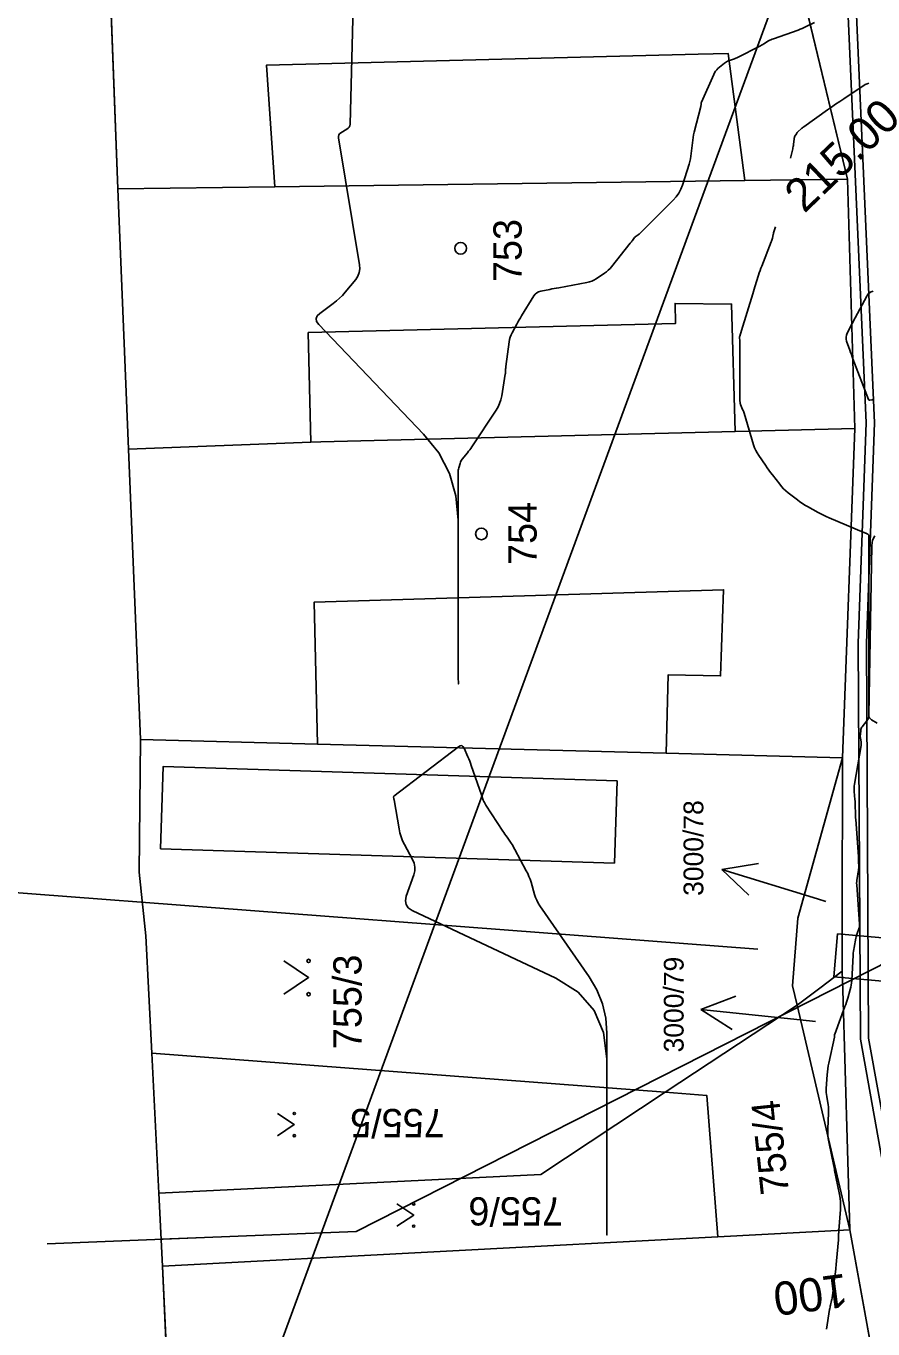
# Model space of a CAD drawing. Extents: x -534481 to -534256, y -1190577 to -1190138.
# Drawn here: x -534435.09 to -534409.62, y -1190436.66 to -1190397.49 of the extents above; entities that cross this region are included whole.
import ezdxf

# ---------------------------------------------------------------- set-up
doc = ezdxf.new("R2010")
doc.units = 0
for name, color, linetype in [('30', 7, 'Continuous'), ('31', 7, 'Continuous'), ('40', 7, 'Continuous'), ('_N_text', 7, 'Continuous'), ('_přístup', 7, 'Continuous'), ('_tenka', 7, 'Continuous'), ('Hranice parcel', 7, 'Continuous'), ('Parcelní čísla', 7, 'Continuous'), ('Polygon budovy', 7, 'Continuous'), ('Pop  PČ popisy', 7, 'Continuous'), ('Vnitřní kresba', 7, 'Continuous'), ('Vrstva 2', 7, 'Continuous'), ('Značky budov', 7, 'Continuous'), ('Značky kultur', 7, 'Continuous')]:
    doc.layers.add(name, color=color, linetype=linetype)

msp = doc.modelspace()

# ---------------------------------------------------------------- linework, layer by layer
at = {"layer": '30'}
for points in [[(-534412.097, -1190401.462), (-534412.031, -1190401.184), (-534412.024, -1190401.15), (-534412.018, -1190401.117), (-534412.012, -1190401.083), (-534412.008, -1190401.049), (-534411.99, -1190400.888), (-534411.987, -1190400.867), (-534411.981, -1190400.846), (-534411.973, -1190400.826), (-534411.963, -1190400.806), (-534411.918, -1190400.73), (-534411.906, -1190400.712), (-534411.893, -1190400.694), (-534411.879, -1190400.678), (-534411.863, -1190400.662), (-534411.781, -1190400.585), (-534411.762, -1190400.567), (-534411.742, -1190400.55), (-534411.721, -1190400.534), (-534411.7, -1190400.519), (-534410.987, -1190400.016), (-534410.864, -1190399.93), (-534410.741, -1190399.845), (-534410.617, -1190399.761), (-534410.492, -1190399.678), (-534409.853, -1190399.254), (-534409.797, -1190399.225), (-534409.746, -1190399.212)], [(-534409.49, -1190418.456), (-534409.659, -1190418.354), (-534409.696, -1190418.326), (-534409.722, -1190418.292), (-534409.738, -1190418.251), (-534409.743, -1190418.205), (-534409.743, -1190412.814), (-534409.745, -1190412.8), (-534409.75, -1190412.787), (-534409.759, -1190412.777), (-534409.772, -1190412.769), (-534409.83, -1190412.742), (-534409.845, -1190412.735), (-534409.86, -1190412.728), (-534409.874, -1190412.722), (-534409.889, -1190412.716), (-534410.937, -1190412.277), (-534411.021, -1190412.241), (-534411.103, -1190412.202), (-534411.185, -1190412.161), (-534411.265, -1190412.118), (-534411.586, -1190411.939), (-534411.664, -1190411.894), (-534411.739, -1190411.846), (-534411.813, -1190411.795), (-534411.885, -1190411.742), (-534412.17, -1190411.523), (-534412.239, -1190411.466), (-534412.304, -1190411.405), (-534412.365, -1190411.34), (-534412.421, -1190411.271), (-534412.641, -1190410.986), (-534412.695, -1190410.915), (-534412.748, -1190410.843), (-534412.8, -1190410.771), (-534412.851, -1190410.697), (-534413.053, -1190410.403), (-534413.101, -1190410.328), (-534413.142, -1190410.25), (-534413.177, -1190410.169), (-534413.206, -1190410.085), (-534413.494, -1190409.135), (-534413.504, -1190409.105), (-534413.514, -1190409.076), (-534413.525, -1190409.047), (-534413.537, -1190409.018), (-534413.601, -1190408.872), (-534413.606, -1190408.858), (-534413.61, -1190408.844), (-534413.613, -1190408.83), (-534413.616, -1190408.815), (-534413.623, -1190408.757), (-534413.624, -1190408.742), (-534413.625, -1190408.728), (-534413.626, -1190408.713), (-534413.626, -1190408.698), (-534413.621, -1190406.998), (-534413.621, -1190406.983), (-534413.621, -1190406.967), (-534413.622, -1190406.952), (-534413.623, -1190406.936), (-534413.629, -1190406.875), (-534413.63, -1190406.86), (-534413.629, -1190406.845), (-534413.627, -1190406.83), (-534413.623, -1190406.815), (-534413.571, -1190406.644), (-534413.23, -1190405.54), (-534413.166, -1190405.331), (-534413.058, -1190404.984), (-534413.036, -1190404.914), (-534413.013, -1190404.845), (-534412.988, -1190404.777), (-534412.962, -1190404.709), (-534412.678, -1190403.984), (-534412.668, -1190403.958), (-534412.659, -1190403.93), (-534412.651, -1190403.903), (-534412.644, -1190403.875), (-534412.619, -1190403.763), (-534412.612, -1190403.735), (-534412.605, -1190403.708), (-534412.597, -1190403.68), (-534412.589, -1190403.653), (-534412.552, -1190403.534)], [(-534409.564, -1190412.815), (-534409.631, -1190412.948), (-534409.655, -1190413.113), (-534409.741, -1190418.207), (-534409.746, -1190418.254), (-534409.757, -1190418.299), (-534409.776, -1190418.34), (-534409.802, -1190418.38), (-534409.943, -1190418.561), (-534409.96, -1190418.585), (-534409.972, -1190418.611), (-534409.981, -1190418.638), (-534409.986, -1190418.667), (-534409.998, -1190418.788), (-534410, -1190418.816), (-534410, -1190418.844), (-534409.999, -1190418.873), (-534409.995, -1190418.901), (-534409.977, -1190419.014), (-534409.974, -1190419.042), (-534409.973, -1190419.07), (-534409.974, -1190419.098), (-534409.978, -1190419.126), (-534410.172, -1190420.287), (-534410.179, -1190420.342), (-534410.183, -1190420.398), (-534410.183, -1190420.453), (-534410.18, -1190420.509), (-534410.159, -1190420.745), (-534410.155, -1190420.795), (-534410.152, -1190420.845), (-534410.15, -1190420.894), (-534410.149, -1190420.944), (-534410.145, -1190421.144), (-534410.143, -1190421.194), (-534410.142, -1190421.244), (-534410.139, -1190421.294), (-534410.136, -1190421.344), (-534410.057, -1190422.459), (-534410.055, -1190422.498), (-534410.053, -1190422.536), (-534410.051, -1190422.575), (-534410.05, -1190422.613), (-534410.047, -1190422.767), (-534410.047, -1190422.806), (-534410.049, -1190422.844), (-534410.053, -1190422.882), (-534410.059, -1190422.92), (-534410.097, -1190423.123), (-534410.104, -1190423.169), (-534410.108, -1190423.216), (-534410.11, -1190423.263), (-534410.108, -1190423.31), (-534410.022, -1190424.498), (-534410.021, -1190424.534), (-534410.024, -1190424.57), (-534410.031, -1190424.605), (-534410.042, -1190424.639), (-534410.091, -1190424.776), (-534410.103, -1190424.81), (-534410.113, -1190424.845), (-534410.123, -1190424.88), (-534410.13, -1190424.916), (-534410.186, -1190425.194), (-534410.197, -1190425.253), (-534410.205, -1190425.311), (-534410.211, -1190425.37), (-534410.216, -1190425.429), (-534410.255, -1190426.19), (-534410.261, -1190426.257), (-534410.27, -1190426.324), (-534410.283, -1190426.39), (-534410.3, -1190426.455), (-534410.375, -1190426.715), (-534410.395, -1190426.779), (-534410.416, -1190426.844), (-534410.437, -1190426.908), (-534410.46, -1190426.971), (-534410.769, -1190427.798), (-534410.772, -1190427.806), (-534410.773, -1190427.813), (-534410.774, -1190427.821), (-534410.775, -1190427.829), (-534410.775, -1190427.86), (-534410.775, -1190427.868), (-534410.776, -1190427.876), (-534410.777, -1190427.884), (-534410.778, -1190427.892), (-534410.944, -1190428.67), (-534410.961, -1190428.757), (-534410.975, -1190428.845), (-534410.986, -1190428.934), (-534410.994, -1190429.023), (-534411.022, -1190429.432), (-534411.024, -1190429.495), (-534411.023, -1190429.557), (-534411.019, -1190429.619), (-534411.01, -1190429.68), (-534410.969, -1190429.927), (-534410.96, -1190429.988), (-534410.955, -1190430.05), (-534410.953, -1190430.112), (-534410.954, -1190430.175), (-534410.975, -1190430.646), (-534410.976, -1190430.745), (-534410.971, -1190430.844), (-534410.961, -1190430.942), (-534410.944, -1190431.039), (-534410.797, -1190431.775), (-534410.79, -1190431.806), (-534410.779, -1190431.868), (-534410.774, -1190431.888), (-534410.772, -1190431.899), (-534410.624, -1190432.622), (-534410.605, -1190432.733), (-534410.594, -1190432.845), (-534410.591, -1190432.958), (-534410.596, -1190433.071), (-534410.645, -1190433.704), (-534410.647, -1190433.728), (-534410.648, -1190433.751), (-534410.649, -1190433.774), (-534410.65, -1190433.797), (-534410.652, -1190433.889), (-534410.652, -1190433.912), (-534410.653, -1190433.935), (-534410.655, -1190433.958), (-534410.657, -1190433.981), (-534410.714, -1190434.619), (-534410.724, -1190434.732), (-534410.736, -1190434.844), (-534410.748, -1190434.957), (-534410.762, -1190435.069), (-534410.837, -1190435.673), (-534410.842, -1190435.708), (-534410.847, -1190435.742), (-534410.854, -1190435.776), (-534410.862, -1190435.81), (-534410.895, -1190435.945), (-534410.903, -1190435.979), (-534410.91, -1190436.013), (-534410.916, -1190436.047), (-534410.922, -1190436.082), (-534411.012, -1190436.668)]]:
    msp.add_lwpolyline(points, dxfattribs=at)
at = {"layer": '31'}
for points in [[(-534411.381, -1190397.388), (-534411.622, -1190397.509), (-534411.683, -1190397.538), (-534411.745, -1190397.565), (-534411.807, -1190397.591), (-534411.871, -1190397.614), (-534412.61, -1190397.873), (-534412.648, -1190397.888), (-534412.686, -1190397.904), (-534412.722, -1190397.922), (-534412.757, -1190397.942), (-534412.898, -1190398.027), (-534412.933, -1190398.048), (-534412.968, -1190398.068), (-534413.004, -1190398.087), (-534413.04, -1190398.106), (-534413.676, -1190398.431), (-534413.71, -1190398.447), (-534413.744, -1190398.463), (-534413.779, -1190398.476), (-534413.815, -1190398.489), (-534413.958, -1190398.535), (-534413.993, -1190398.548), (-534414.026, -1190398.565), (-534414.057, -1190398.584), (-534414.087, -1190398.607), (-534414.279, -1190398.773), (-534414.318, -1190398.81), (-534414.352, -1190398.852), (-534414.382, -1190398.896), (-534414.406, -1190398.945), (-534414.776, -1190399.782), (-534414.78, -1190399.793), (-534414.783, -1190399.803), (-534414.785, -1190399.814), (-534414.786, -1190399.825), (-534414.789, -1190399.869), (-534414.79, -1190399.88), (-534414.791, -1190399.891), (-534414.793, -1190399.902), (-534414.795, -1190399.913), (-534414.993, -1190400.688), (-534415.012, -1190400.766), (-534415.028, -1190400.846), (-534415.04, -1190400.925), (-534415.05, -1190401.006), (-534415.082, -1190401.328), (-534415.092, -1190401.408), (-534415.107, -1190401.488), (-534415.125, -1190401.566), (-534415.148, -1190401.644), (-534415.349, -1190402.273), (-534415.398, -1190402.399), (-534415.46, -1190402.517), (-534415.537, -1190402.627), (-534415.627, -1190402.728), (-534416.627, -1190403.728), (-534416.639, -1190403.74), (-534416.652, -1190403.75), (-534416.665, -1190403.76), (-534416.679, -1190403.77), (-534416.736, -1190403.805), (-534416.75, -1190403.814), (-534416.763, -1190403.825), (-534416.774, -1190403.837), (-534416.785, -1190403.85), (-534416.854, -1190403.944), (-534416.869, -1190403.965), (-534416.884, -1190403.985), (-534416.899, -1190404.004), (-534416.915, -1190404.024), (-534417.476, -1190404.727), (-534417.525, -1190404.784), (-534417.578, -1190404.836), (-534417.635, -1190404.883), (-534417.695, -1190404.927), (-534417.946, -1190405.091), (-534418.01, -1190405.128), (-534418.077, -1190405.159), (-534418.147, -1190405.183), (-534418.219, -1190405.2), (-534419.069, -1190405.359), (-534419.136, -1190405.371), (-534419.204, -1190405.384), (-534419.271, -1190405.397), (-534419.339, -1190405.41), (-534419.608, -1190405.464), (-534419.672, -1190405.483), (-534419.728, -1190405.513), (-534419.775, -1190405.555), (-534419.816, -1190405.608), (-534420.184, -1190406.201), (-534420.222, -1190406.264), (-534420.259, -1190406.327), (-534420.296, -1190406.391), (-534420.331, -1190406.456), (-534420.47, -1190406.715), (-534420.502, -1190406.781), (-534420.527, -1190406.849), (-534420.546, -1190406.918), (-534420.559, -1190406.99), (-534420.657, -1190407.725), (-534420.659, -1190407.744), (-534420.661, -1190407.764), (-534420.663, -1190407.783), (-534420.664, -1190407.802), (-534420.667, -1190407.88), (-534420.668, -1190407.9), (-534420.67, -1190407.919), (-534420.672, -1190407.938), (-534420.675, -1190407.958), (-534420.783, -1190408.613), (-534420.808, -1190408.727), (-534420.845, -1190408.836), (-534420.892, -1190408.94), (-534420.951, -1190409.04), (-534421.684, -1190410.148), (-534421.714, -1190410.193), (-534421.745, -1190410.236), (-534421.778, -1190410.279), (-534421.811, -1190410.321), (-534421.971, -1190410.517), (-534421.991, -1190410.546), (-534422.009, -1190410.575), (-534422.024, -1190410.607), (-534422.035, -1190410.64), (-534422.075, -1190410.776), (-534422.083, -1190410.811), (-534422.089, -1190410.845), (-534422.093, -1190410.88), (-534422.094, -1190410.915), (-534422.094, -1190416.759), (-534422.094, -1190416.802), (-534422.094, -1190416.844), (-534422.093, -1190416.887), (-534422.092, -1190416.93), (-534422.088, -1190417.101), (-534422.087, -1190417.144), (-534422.086, -1190417.187), (-534422.086, -1190417.23), (-534422.085, -1190417.272), (-534422.086, -1190417.23), (-534422.086, -1190417.187), (-534422.087, -1190417.144), (-534422.088, -1190417.101), (-534422.092, -1190416.93), (-534422.093, -1190416.887), (-534422.094, -1190416.844), (-534422.094, -1190416.802), (-534422.094, -1190416.759), (-534422.094, -1190412.345), (-534422.159, -1190411.621), (-534422.354, -1190410.949), (-534422.678, -1190410.329), (-534423.131, -1190409.761), (-534426.285, -1190406.464), (-534426.349, -1190406.375), (-534426.365, -1190406.29), (-534426.334, -1190406.21), (-534426.256, -1190406.134), (-534425.85, -1190405.835), (-534425.752, -1190405.759), (-534425.659, -1190405.677), (-534425.572, -1190405.589), (-534425.49, -1190405.495), (-534425.174, -1190405.108), (-534425.107, -1190405.008), (-534425.066, -1190404.902), (-534425.049, -1190404.789), (-534425.057, -1190404.669), (-534425.691, -1190400.858), (-534425.692, -1190400.81), (-534425.681, -1190400.767), (-534425.656, -1190400.732), (-534425.617, -1190400.702), (-534425.437, -1190400.597), (-534425.397, -1190400.567), (-534425.368, -1190400.531), (-534425.351, -1190400.488), (-534425.344, -1190400.439), (-534425.133, -1190392.149)], [(-534409.609, -1190408.718), (-534409.623, -1190408.723), (-534409.638, -1190408.727), (-534409.653, -1190408.73), (-534409.713, -1190408.741), (-534409.727, -1190408.742), (-534409.738, -1190408.738), (-534409.747, -1190408.73), (-534409.754, -1190408.718), (-534410.219, -1190407.501), (-534410.244, -1190407.435), (-534410.268, -1190407.37), (-534410.292, -1190407.305), (-534410.315, -1190407.239), (-534410.411, -1190406.969), (-534410.426, -1190406.907), (-534410.429, -1190406.846), (-534410.418, -1190406.787), (-534410.394, -1190406.728), (-534410.24, -1190406.436), (-534410.149, -1190406.261), (-534409.807, -1190405.61), (-534409.771, -1190405.555), (-534409.725, -1190405.512), (-534409.671, -1190405.482), (-534409.608, -1190405.463)]]:
    msp.add_lwpolyline(points, dxfattribs=at)
msp.add_lwpolyline([(-534417.621, -1190427.776), (-534417.621, -1190433.845), (-534417.621, -1190428.541), (-534417.717, -1190427.753), (-534418.004, -1190427.087), (-534418.483, -1190426.543), (-534419.154, -1190426.12), (-534423.474, -1190424.08), (-534423.591, -1190424.003), (-534423.659, -1190423.907), (-534423.68, -1190423.791), (-534423.652, -1190423.654), (-534423.428, -1190423.016), (-534423.398, -1190422.896), (-534423.395, -1190422.779), (-534423.417, -1190422.664), (-534423.464, -1190422.55), (-534423.707, -1190422.101), (-534423.763, -1190421.987), (-534423.809, -1190421.87), (-534423.845, -1190421.749), (-534423.871, -1190421.625), (-534424.02, -1190420.753), (-534424.023, -1190420.735), (-534424.027, -1190420.717), (-534424.034, -1190420.68), (-534424.034, -1190420.672), (-534424.033, -1190420.664), (-534424.029, -1190420.657), (-534424.023, -1190420.651), (-534422.084, -1190419.159), (-534422.031, -1190419.13), (-534421.986, -1190419.127), (-534421.947, -1190419.151), (-534421.915, -1190419.202), (-534421.8, -1190419.46), (-534421.772, -1190419.524), (-534421.746, -1190419.59), (-534421.721, -1190419.655), (-534421.697, -1190419.722), (-534421.393, -1190420.603), (-534421.338, -1190420.764), (-534421.323, -1190420.804), (-534421.305, -1190420.842), (-534421.285, -1190420.879), (-534421.263, -1190420.915), (-534420.746, -1190421.695), (-534420.715, -1190421.741), (-534420.685, -1190421.786), (-534420.654, -1190421.832), (-534420.623, -1190421.877), (-534420.5, -1190422.059), (-534420.47, -1190422.104), (-534420.441, -1190422.151), (-534420.413, -1190422.198), (-534420.387, -1190422.246), (-534420.043, -1190422.888), (-534420, -1190422.972), (-534419.963, -1190423.059), (-534419.929, -1190423.147), (-534419.901, -1190423.237), (-534419.796, -1190423.601), (-534419.766, -1190423.691), (-534419.729, -1190423.777), (-534419.686, -1190423.86), (-534419.635, -1190423.939), (-534418.151, -1190426.079), (-534417.919, -1190426.472), (-534417.753, -1190426.886), (-534417.654, -1190427.32)], close=True, dxfattribs=at)
at = {"layer": '_N_text'}
msp.add_lwpolyline([(-534406.078, -1190512.511), (-534434.703, -1190456.89), (-534410.94, -1190392.232)], dxfattribs=at)
at = {"layer": '_přístup'}
msp.add_line((-534442.17, -1190423.028), (-534413.082, -1190425.244), dxfattribs=at)
msp.add_lwpolyline([(-534417.39, -1190422.659), (-534417.312, -1190420.188), (-534430.965, -1190419.755), (-534431.043, -1190422.227)], close=True, dxfattribs=at)
at = {"layer": '_tenka'}
for points in [[(-534405.407, -1190514.348), (-534394.258, -1190501.982), (-534392.12, -1190496.869), (-534393.492, -1190488.211), (-534397.35, -1190478.035), (-534403.219, -1190464.54), (-534405.491, -1190456.905), (-534409.051, -1190433.21), (-534409.998, -1190427.948), (-534410.066, -1190416.042), (-534409.827, -1190409.421), (-534410.645, -1190390.84)], [(-534405.057, -1190514.333), (-534394.044, -1190502.118), (-534391.862, -1190496.9), (-534393.249, -1190488.146), (-534397.118, -1190477.94), (-534402.983, -1190464.455), (-534405.247, -1190456.85), (-534408.804, -1190433.17), (-534409.748, -1190427.925), (-534409.816, -1190416.046), (-534409.577, -1190409.42), (-534410.397, -1190390.795)]]:
    msp.add_lwpolyline(points, dxfattribs=at)
at = {"layer": 'Hranice parcel'}
for p, q in [((-534410.38, -1190402.1), (-534412.44, -1190393.55)), ((-534432.64, -1190394.16), (-534432.33, -1190402.39)), ((-534410.16, -1190409.59), (-534410.38, -1190402.1)), ((-534432.33, -1190402.39), (-534432.01, -1190410.21)), ((-534410.53, -1190419.49), (-534410.16, -1190409.59)), ((-534432.01, -1190410.21), (-534431.64, -1190418.94)), ((-534415.87, -1190429.55), (-534411.9, -1190426.93)), ((-534410.31, -1190433.69), (-534411.9, -1190426.93)), ((-534431.3, -1190428.37), (-534415.87, -1190429.55)), ((-534431.3, -1190428.37), (-534431.09, -1190432.58)), ((-534431.09, -1190432.58), (-534430.98, -1190434.78)), ((-534414.28, -1190433.9), (-534430.98, -1190434.78)), ((-534410.31, -1190433.69), (-534414.28, -1190433.9)), ((-534407.58, -1190448.75), (-534410.31, -1190433.69)), ((-534430.98, -1190434.78), (-534430.23, -1190451.45))]:
    msp.add_line(p, q, dxfattribs=at)
for points in [[(-534432.33, -1190402.39), (-534427.61, -1190402.33), (-534413.47, -1190402.14), (-534410.38, -1190402.1)], [(-534432.01, -1190410.21), (-534426.52, -1190410), (-534426.22, -1190409.99), (-534413.76, -1190409.68), (-534410.16, -1190409.59)], [(-534431.64, -1190418.94), (-534431.68, -1190422.93), (-534431.48, -1190424.85), (-534431.3, -1190428.37)], [(-534431.64, -1190418.94), (-534426.32, -1190419.08), (-534415.84, -1190419.35), (-534410.53, -1190419.49)], [(-534411.9, -1190426.93), (-534412.04, -1190426.35), (-534411.88, -1190424.31), (-534410.53, -1190419.49)], [(-534410.53, -1190419.49), (-534410.54, -1190424.42), (-534410.54, -1190425.91)], [(-534411.9, -1190426.93), (-534411.22, -1190426.42), (-534410.54, -1190425.91)], [(-534410.54, -1190425.91), (-534410.52, -1190426.47), (-534410.31, -1190433.69)], [(-534431.09, -1190432.58), (-534419.61, -1190432.02), (-534415.87, -1190429.55)], [(-534415.87, -1190429.55), (-534414.61, -1190429.65), (-534414.28, -1190433.9)]]:
    msp.add_lwpolyline(points, dxfattribs=at)
at = {"layer": 'Polygon budovy'}
for points in [[(-534432.64, -1190394.16), (-534432.33, -1190402.39), (-534427.61, -1190402.33), (-534427.86, -1190398.67), (-534414.87, -1190398.34), (-534413.97, -1190398.32), (-534413.47, -1190402.14), (-534410.38, -1190402.1), (-534412.44, -1190393.55), (-534415.89, -1190393.7), (-534421.6, -1190393.94), (-534427.8, -1190394.2)], [(-534410.38, -1190402.1), (-534413.47, -1190402.14), (-534427.61, -1190402.33), (-534432.33, -1190402.39), (-534432.01, -1190410.21), (-534426.52, -1190410), (-534426.6, -1190406.71), (-534415.56, -1190406.44), (-534415.57, -1190405.83), (-534413.87, -1190405.85), (-534413.76, -1190409.68), (-534410.16, -1190409.59)], [(-534432.01, -1190410.21), (-534431.64, -1190418.94), (-534426.32, -1190419.08), (-534426.42, -1190414.81), (-534414.11, -1190414.44), (-534414.2, -1190417.03), (-534415.78, -1190417), (-534415.84, -1190419.35), (-534410.53, -1190419.49), (-534410.16, -1190409.59), (-534413.76, -1190409.68), (-534426.22, -1190409.99), (-534426.52, -1190410)], [(-534422.89, -1190441.14), (-534413.83, -1190440.6), (-534412.6, -1190449.51), (-534407.58, -1190448.75), (-534410.31, -1190433.69), (-534414.28, -1190433.9), (-534430.98, -1190434.78), (-534430.23, -1190451.45), (-534422.73, -1190450.69), (-534422.94, -1190447.02), (-534422.61, -1190447)]]:
    msp.add_lwpolyline(points, close=True, dxfattribs=at)
at = {"layer": 'Pop  PČ popisy'}
for p, q in [((-534414.16, -1190422.853), (-534413.056, -1190422.667)), ((-534411.29, -1190423.73), (-534414.16, -1190422.853)), ((-534414.16, -1190422.853), (-534413.349, -1190423.624)), ((-534411.04, -1190423.81), (-534411.29, -1190423.73)), ((-534414.795, -1190427.056), (-534413.746, -1190426.663)), ((-534411.81, -1190427.37), (-534414.795, -1190427.056)), ((-534414.795, -1190427.056), (-534413.851, -1190427.659)), ((-534411.35, -1190427.42), (-534411.81, -1190427.37))]:
    msp.add_line(p, q, dxfattribs=at)
at = {"layer": 'Vnitřní kresba'}
msp.add_lwpolyline([(-534407.407, -1190426.376), (-534407.295, -1190425.083), (-534410.68, -1190424.789), (-534410.792, -1190426.083)], close=True, dxfattribs=at)
at = {"layer": 'Vrstva 2'}
for points in [[(-534388.755, -1190426.81), (-534407.258, -1190424.643), (-534412.763, -1190427.438), (-534425.162, -1190433.733), (-534429.719, -1190433.916), (-534434.452, -1190434.105)], [(-534388.755, -1190426.81), (-534407.258, -1190424.643), (-534412.763, -1190427.438), (-534425.162, -1190433.733), (-534429.719, -1190433.916), (-534431.021, -1190433.968)], [(-534388.755, -1190426.81), (-534407.258, -1190424.643), (-534412.763, -1190427.438), (-534425.162, -1190433.733), (-534429.719, -1190433.916), (-534431.021, -1190433.968)]]:
    msp.add_lwpolyline(points, dxfattribs=at)
at = {"layer": 'Značky budov'}
for centre in [(-534422.017, -1190404.175), (-534421.394, -1190412.762)]:
    msp.add_circle(centre, 0.175, dxfattribs=at)
at = {"layer": 'Značky kultur'}
for points in [[(-534427.338, -1190426.602), (-534426.588, -1190426.102), (-534427.338, -1190425.602)], [(-534427.523, -1190430.857), (-534427.02, -1190430.522), (-534427.523, -1190430.187)], [(-534423.932, -1190433.576), (-534423.429, -1190433.241), (-534423.932, -1190432.906)]]:
    msp.add_lwpolyline(points, dxfattribs=at)
for centre, radius in [((-534426.588, -1190425.602), 0.05), ((-534426.588, -1190426.602), 0.05), ((-534427.02, -1190430.187), 0.0335), ((-534427.02, -1190430.857), 0.0335), ((-534423.429, -1190432.906), 0.0335), ((-534423.429, -1190433.576), 0.0335)]:
    msp.add_circle(centre, radius, dxfattribs=at)

# ---------------------------------------------------------------- texts
at = {"layer": '40'}
msp.add_text('215.00', height=1, rotation=43.7488, dxfattribs=at).set_placement((-534411.684, -1190403.143))
at = {"layer": '_N_text'}
msp.add_text('100', height=1, rotation=187.318, dxfattribs=at).set_placement((-534410.45, -1190434.999))
at = {"layer": 'Parcelní čísla'}
for s, height, rotation, p in [('753', 0.85, 90, (-534420.183, -1190405.191)), ('754', 0.85, 90, (-534419.731, -1190413.696)), ('3000/78', 0.595, 90, (-534414.72, -1190423.645)), ('755/3', 0.85, 90, (-534424.998, -1190428.253)), ('3000/79', 0.595, 90, (-534415.312, -1190428.351)), ('755/5', 0.85, 180, (-534422.495, -1190430.05)), ('755/4', 0.85, 96, (-534412.14, -1190432.582)), ('755/6', 0.85, 180, (-534418.938, -1190432.705))]:
    msp.add_text(s, height=height, rotation=rotation, dxfattribs=at).set_placement(p)

doc.saveas('drawing.dxf')
